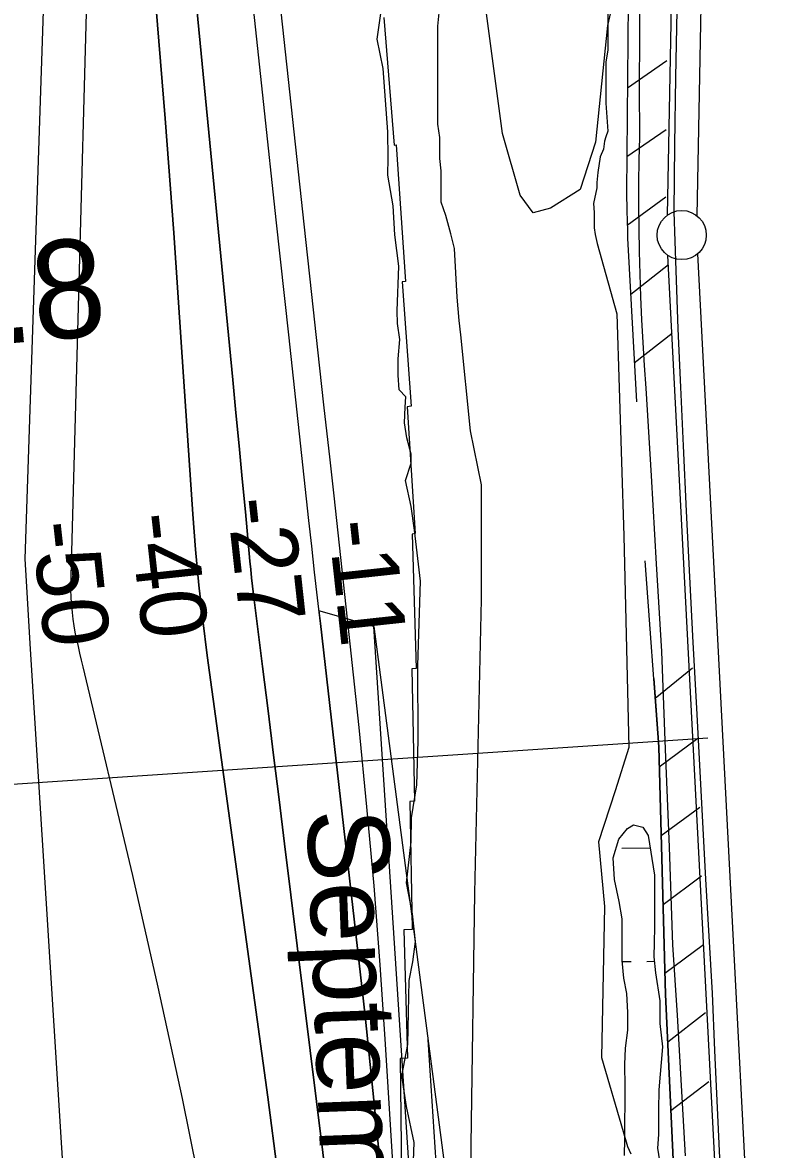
# Model space of a CAD drawing. Extents: x 3568792 to 3606828, y 529143 to 554785.
# Drawn here: x 3578425 to 3579198, y 535909 to 537056 of the extents above; entities that cross this region are included whole.
import ezdxf

# ---------------------------------------------------------------- set-up
doc = ezdxf.new("R2010")
doc.units = 0
for name, color, linetype in [('V-FLOD-BASE', 7, 'Continuous'), ('V-LEVE-TOET', 7, 'Continuous'), ('V-RIVR-EDGE', 7, 'Continuous'), ('V-RIVR-IDEN', 7, 'Continuous'), ('V-RIVR-RANG', 7, 'Continuous'), ('V-RRAP-FSHR', 7, 'Continuous'), ('V-RRAP-RVMT', 7, 'Continuous'), ('V-SITE-VEGE', 7, 'Continuous'), ('V-SURV-IDEN', 7, 'Continuous'), ('V-SURV-LINE', 7, 'Continuous'), ('V-TOPO-DPTH', 7, 'Continuous'), ('V-TOPO-MAJR', 7, 'Continuous'), ('V-TOPO-MINR', 7, 'Continuous'), ('V-WETL-SWMP', 7, 'Continuous')]:
    doc.layers.add(name, color=color, linetype=linetype)

msp = doc.modelspace()

# ---------------------------------------------------------------- linework, layer by layer
at = {"layer": 'V-FLOD-BASE'}
msp.add_lwpolyline([(3579092, 537136.5), (3579090.6, 537068.2), (3579089.3, 536999.9), (3579088.3, 536931.5), (3579087.4, 536863.2), (3579089.4, 536803.7), (3579091.7, 536744.2), (3579094.3, 536684.8), (3579097.1, 536625.3), (3579100.1, 536558.6), (3579103.3, 536491.8), (3579106.8, 536425.1), (3579110.4, 536358.4), (3579113.4, 536300.4), (3579116.5, 536242.4), (3579119.7, 536184.4), (3579123, 536126.5), (3579126.3, 536068.5), (3579128.8, 536010.2), (3579131.5, 535951.9), (3579134.4, 535893.6)], dxfattribs=at)
at = {"layer": 'V-LEVE-TOET'}
msp.add_lwpolyline([(3579052.7, 537091.9), (3579052.4, 537041), (3579052.3, 536990), (3579052.5, 536939.1), (3579052, 536915.9), (3579051.7, 536892.7), (3579051.7, 536869.4), (3579051.8, 536846.2), (3579052.2, 536823), (3579052.8, 536799.8), (3579053.6, 536776.6), (3579054.7, 536753.4), (3579055.9, 536730.2), (3579057.4, 536707), (3579059.1, 536683.9), (3579064.4, 536594.6), (3579069.6, 536505.3), (3579074.8, 536416.1), (3579078.8, 536316.6), (3579082.7, 536217.1), (3579086.2, 536117.7), (3579090.7, 536046.1), (3579095, 535974.6), (3579098.9, 535903)], dxfattribs=at)
at = {"layer": 'V-RIVR-EDGE'}
msp.add_lwpolyline([(3578821.6, 535860), (3578823.6, 535916.4), (3578815.7, 535953.2), (3578810.9, 535984.4), (3578817.1, 536016.3), (3578818.5, 536081.2), (3578822.2, 536100.2), (3578824.7, 536121.1), (3578821.7, 536149.2), (3578815.6, 536180.5), (3578820.6, 536222.2), (3578820.7, 536246.7), (3578826.3, 536280.4), (3578827.6, 536325.1), (3578827.2, 536401.7), (3578829.9, 536487.4), (3578823.9, 536539.5), (3578820.3, 536563.5), (3578814.8, 536589.8), (3578820.4, 536607.6), (3578820.4, 536616.8), (3578816.1, 536633.3), (3578813.7, 536648.6), (3578814.4, 536664.6), (3578815, 536675), (3578808.3, 536682.3), (3578807.1, 536697.1), (3578807.2, 536713.6), (3578809, 536733.2), (3578806.6, 536749.8), (3578806.1, 536762.6), (3578808, 536808), (3578803.8, 536839.8), (3578802, 536869.2), (3578796.6, 536900.5), (3578797.2, 536918.3), (3578796.7, 536944.6), (3578792, 537009), (3578785.9, 537039), (3578790.3, 537069.6)], dxfattribs=at)
at = {"layer": 'V-RIVR-RANG'}
msp.add_line((3579122.1, 536327.7), (3578124.3, 536261.4), dxfattribs=at)
at = {"layer": 'V-RRAP-FSHR'}
for p, q in [((3579040.2, 536989.4), (3579080.4, 537017.1)), ((3579039.6, 536919.4), (3579079.8, 536947.1)), ((3579040.1, 536849.5), (3579079.4, 536878.5)), ((3579043.6, 536779.5), (3579082, 536809.7)), ((3579047.3, 536709.6), (3579085.8, 536739.8)), ((3579068.5, 536368.5), (3579106.4, 536399.4)), ((3579072.7, 536298.7), (3579112, 536327.7)), ((3579074.6, 536228.7), (3579113.8, 536257.7)), ((3579076.5, 536158.7), (3579115.7, 536187.8)), ((3579078.3, 536088.7), (3579117.6, 536117.8)), ((3579081.2, 536018.8), (3579119.8, 536048.6)), ((3579084.4, 535948.9), (3579123.1, 535978.7))]:
    msp.add_line(p, q, dxfattribs=at)
for points in [[(3579046.3, 537362.9), (3579041.3, 537115.1), (3579039.2, 536882.9), (3579039.7, 536864.2), (3579040.3, 536844), (3579040.5, 536836.6), (3579049.5, 536670.1)], [(3579186.7, 534602.9), (3579174.2, 534707.2), (3579144.2, 534996.7), (3579130.5, 535127.8), (3579117, 535281.1), (3579108.5, 535490.5), (3579094.3, 535738.6), (3579078.9, 536066.9), (3579072.2, 536318.9), (3579058.2, 536508.1)], [(3579067.1, 536388.4), (3579072.2, 536318.9), (3579078.9, 536066.9), (3579094.3, 535738.6), (3579099, 535656.3)]]:
    msp.add_lwpolyline(points, dxfattribs=at)
at = {"layer": 'V-RRAP-RVMT'}
for p, q in [((3578792.8, 537060.9), (3578803.1, 536931.2)), ((3578803.1, 536931.2), (3578805.3, 536931.3)), ((3578805.3, 536931.3), (3578814.8, 536792.2)), ((3578814.8, 536792.2), (3578811.2, 536791.9)), ((3578811.2, 536791.9), (3578820.4, 536665.4)), ((3578820.4, 536665.4), (3578816.4, 536665)), ((3578816.4, 536665), (3578824.4, 536536)), ((3578824.4, 536536), (3578821.5, 536535.4)), ((3578821.5, 536535.4), (3578825.4, 536398.6)), ((3578825.4, 536398.6), (3578821.2, 536398.3)), ((3578821.2, 536398.3), (3578823.7, 536263.7)), ((3578823.7, 536263.7), (3578819, 536263.5)), ((3578819, 536263.5), (3578821.6, 536133.3)), ((3578821.6, 536133.3), (3578813, 536132.9)), ((3578813, 536132.9), (3578816.6, 536002.2)), ((3578816.6, 536002.2), (3578809.1, 536002.1)), ((3578809.1, 536002.1), (3578810.9, 535875))]:
    msp.add_line(p, q, dxfattribs=at)
at = {"layer": 'V-SITE-VEGE'}
for p, q in [((3578847.5, 537052.1), (3578849.7, 537072.5)), ((3579020.5, 537074.3), (3579020.5, 537027.9)), ((3578847.5, 536952.5), (3578847.5, 537052.1)), ((3579020.5, 537027.9), (3579018.3, 537015.4)), ((3579018.3, 537015.4), (3579018.3, 536973.6)), ((3579018.3, 536973.6), (3579020.5, 536945.2)), ((3578849.7, 536938.9), (3578847.5, 536952.5)), ((3579020.5, 536945.2), (3579018.3, 536939.6)), ((3578849.7, 536917.4), (3578849.7, 536938.9)), ((3579017.1, 536935.1), (3579016, 536927.1)), ((3579018.3, 536939.6), (3579017.1, 536935.1)), ((3579016, 536927.1), (3579012.6, 536919.2)), ((3578850.9, 536904.9), (3578849.7, 536917.4)), ((3579012.6, 536919.2), (3579010.3, 536903.4)), ((3578850.9, 536873.2), (3578850.9, 536904.9)), ((3579010.3, 536903.4), (3579009.2, 536893.2)), ((3579009.2, 536887.5), (3579005.8, 536871.7)), ((3579009.2, 536893.2), (3579009.2, 536887.5)), ((3578855.7, 536859.5), (3578850.9, 536873.2)), ((3579005.8, 536871.7), (3579006.6, 536862.6)), ((3578860.9, 536840.9), (3578855.7, 536859.5)), ((3579006.6, 536862.6), (3579006.6, 536847.1)), ((3579006.6, 536847.1), (3579007.6, 536840.3)), ((3578864.5, 536825.8), (3578860.9, 536840.9)), ((3579007.6, 536840.3), (3579009.4, 536831.1)), ((3579009.4, 536831.1), (3579029.4, 536759.3)), ((3578867.1, 536776.5), (3578864.5, 536825.8)), ((3578869.2, 536752.7), (3578867.1, 536776.5)), ((3578870.8, 536738.2), (3578869.2, 536752.7)), ((3579029.4, 536759.3), (3579036.6, 536533.8)), ((3578880.9, 536640.4), (3578870.8, 536738.2)), ((3578891.9, 536585.5), (3578880.9, 536640.4)), ((3578892, 536468.8), (3578891.9, 536585.5)), ((3579036.6, 536533.8), (3579041.8, 536318.2)), ((3578885.3, 536170.4), (3578892, 536468.8)), ((3579041.8, 536318.2), (3579027.9, 536274.3)), ((3579027.9, 536274.3), (3579010.9, 536222.4)), ((3579010.9, 536222.4), (3579017, 536156.6)), ((3578881.5, 535914), (3578885.3, 536170.4)), ((3579017, 536156.6), (3579014.1, 536002.9)), ((3579014.1, 536002.9), (3579036.1, 535927.7)), ((3579036.1, 535927.7), (3579040.4, 535912.6)), ((3578880.8, 535870), (3578881.5, 535914)), ((3579040.4, 535912.6), (3579043.6, 535905.1))]:
    msp.add_line(p, q, dxfattribs=at)
at = {"layer": 'V-SURV-LINE'}
for points in [[(3579080.9, 536859.9), (3579109.8, 538371.5)], [(3579139.8, 538370.9), (3579110.8, 536859.3)], [(3579167.9, 535153.4), (3579081.5, 536818.9)], [(3579111.5, 536820.4), (3579197.9, 535155)]]:
    msp.add_lwpolyline(points, dxfattribs=at)
msp.add_circle((3579095.5, 536839.6), 25, dxfattribs=at)
at = {"layer": 'V-TOPO-DPTH'}
for points in [[(3578568.1, 537426.5), (3578639.1, 536692.4), (3578642.3, 536658.8), (3578645.5, 536625.2), (3578648.7, 536591.6), (3578651.9, 536558), (3578656.5, 536507.8), (3578657.4, 536499.3), (3578658.2, 536490.8), (3578659.2, 536482.4), (3578660.2, 536473.9), (3578669.3, 536400.6), (3578674.9, 536355.6), (3578680.5, 536310.5), (3578686.1, 536265.4), (3578691.7, 536220.3), (3578776.4, 535537.7)], [(3578776.4, 535537.7), (3578691.7, 536220.3), (3578686.1, 536265.4), (3578680.5, 536310.5), (3578674.9, 536355.6), (3578669.3, 536400.6), (3578660.2, 536473.9), (3578659.2, 536482.4), (3578658.2, 536490.8), (3578657.4, 536499.3), (3578656.5, 536507.8), (3578651.9, 536558), (3578648.7, 536591.6), (3578645.5, 536625.2), (3578642.3, 536658.8), (3578639.1, 536692.4), (3578568.1, 537426.5)], [(3578791.6, 535866.8), (3578782.9, 535956.1), (3578773.5, 536045.4), (3578728.1, 536444.4), (3578725.1, 536470.6), (3578722.2, 536496.8), (3578719.3, 536523), (3578716.4, 536549.2), (3578695.9, 536738.1), (3578683.2, 536855.2), (3578670.6, 536972.4), (3578658.2, 537089.6)], [(3578560.7, 537074.2), (3578570.2, 536958.1), (3578579, 536841.8), (3578587.1, 536725.5), (3578598.5, 536555.6), (3578601.3, 536519.6), (3578604.6, 536483.6), (3578608.6, 536447.7), (3578613.1, 536411.9), (3578674.6, 535962.6), (3578684.5, 535886.5)], [(3578560.7, 537074.2), (3578570.2, 536958.1), (3578579, 536841.8), (3578587.1, 536725.5), (3578598.5, 536555.6), (3578601.3, 536519.6), (3578604.6, 536483.6), (3578608.6, 536447.7), (3578613.1, 536411.9), (3578674.6, 535962.6), (3578684.5, 535886.5)], [(3578774.2, 534596.2), (3578837.8, 535354.7), (3578839.7, 535380.4), (3578841.2, 535406.1), (3578842.2, 535431.8), (3578842.7, 535457.5), (3578842.9, 535470.1), (3578842.9, 535489.5), (3578842.6, 535508.9), (3578841.9, 535528.3), (3578840.8, 535547.7), (3578782.5, 536441.3), (3578726.6, 536457.5)], [(3578726.6, 536457.5), (3578728.1, 536444.4), (3578773.5, 536045.4), (3578782.9, 535956.1), (3578791.6, 535866.8), (3578798.9, 535777.3), (3578805.3, 535687.7), (3578816, 535520.7), (3578816.2, 535514.6), (3578816.1, 535508.5), (3578815.6, 535502.4), (3578814.8, 535496.3), (3578800.6, 535409.1), (3578793.1, 535359.3), (3578786.5, 535309.5), (3578781, 535259.5), (3578776.3, 535209.4), (3578726.7, 534595.8)], [(3578774.2, 534596.2), (3578837.8, 535354.7), (3578839.7, 535380.4), (3578841.2, 535406.1), (3578842.2, 535431.8), (3578842.7, 535457.5), (3578842.9, 535470.1), (3578842.9, 535489.5), (3578842.6, 535508.9), (3578841.9, 535528.3), (3578840.8, 535547.7), (3578782.5, 536441.3)], [(3578782.5, 536441.3), (3578892.7, 535600.9), (3578898.3, 535515), (3578898.4, 535512.5), (3578898.5, 535507.5), (3578898.5, 535502.6), (3578898.4, 535500.1), (3578898.1, 535495.1), (3578879.8, 535268.9), (3578877.3, 535154.1), (3578883.6, 535040.3), (3578896.8, 534964.6), (3578774.2, 534596.2)]]:
    msp.add_lwpolyline(points, dxfattribs=at)
at = {"layer": 'V-TOPO-MAJR'}
msp.add_lwpolyline([(3578610.9, 535847.1), (3578588.1, 535961.1), (3578563.3, 536074.6), (3578537.4, 536188), (3578487, 536400.3), (3578485.3, 536407.3), (3578483.7, 536414.3), (3578482.1, 536421.2), (3578480.4, 536428.2), (3578480.2, 536429), (3578478.9, 536435.6), (3578477.7, 536442.2), (3578476.8, 536448.9), (3578476.1, 536455.6), (3578475, 536467.6), (3578474.9, 536469.1), (3578474.7, 536473.9), (3578474.6, 536476), (3578474.5, 536480.2), (3578499.2, 537389.8)], dxfattribs=at)
at = {"layer": 'V-TOPO-MINR'}
for points in [[(3578776.4, 535537.7), (3578691.7, 536220.3), (3578686.1, 536265.4), (3578680.5, 536310.5), (3578674.9, 536355.6), (3578669.3, 536400.6), (3578660.2, 536473.9), (3578659.2, 536482.4), (3578658.2, 536490.8), (3578657.4, 536499.3), (3578656.5, 536507.8), (3578651.9, 536558), (3578648.7, 536591.6), (3578645.5, 536625.2), (3578642.3, 536658.8), (3578639.1, 536692.4), (3578568.1, 537426.5)], [(3578473.5, 535781.4), (3578433.5, 536418.4), (3578432.1, 536441.4), (3578430.7, 536464.4), (3578429.3, 536487.4), (3578428, 536510.4), (3578458.4, 537422.4)], [(3578824.4, 535529.8), (3578794.4, 536016.7), (3578788.9, 536097.3), (3578782.7, 536177.7), (3578775.4, 536258.1), (3578767.4, 536338.5), (3578758.4, 536423.8), (3578754.4, 536461.4), (3578750.3, 536499.1), (3578746.2, 536536.7), (3578742.1, 536574.3), (3578738, 536611.1), (3578731.8, 536667), (3578725.6, 536723), (3578719.5, 536779.1), (3578713.4, 536835.1), (3578654.3, 537380.1)], [(3578791.6, 535866.8), (3578782.9, 535956.1), (3578773.5, 536045.4), (3578728.1, 536444.4), (3578725.1, 536470.6), (3578722.2, 536496.8), (3578719.3, 536523), (3578716.4, 536549.2), (3578695.9, 536738.1), (3578683.2, 536855.2), (3578670.6, 536972.4), (3578658.2, 537089.6)], [(3578684.5, 535886.5), (3578674.6, 535962.6), (3578613.1, 536411.9), (3578608.6, 536447.7), (3578604.6, 536483.6), (3578601.3, 536519.6), (3578598.5, 536555.6), (3578587.1, 536725.5), (3578579, 536841.8), (3578570.2, 536958.1), (3578560.7, 537074.2)], [(3578774.2, 534596.2), (3578837.8, 535354.7), (3578839.7, 535380.4), (3578841.2, 535406.1), (3578842.2, 535431.8), (3578842.7, 535457.5), (3578842.9, 535470.1), (3578842.9, 535489.5), (3578842.6, 535508.9), (3578841.9, 535528.3), (3578840.8, 535547.7), (3578782.5, 536441.3)], [(3578797.4, 534596.4), (3578868.1, 535425.3), (3578869.1, 535439.3), (3578869.9, 535453.3), (3578870.4, 535467.3), (3578870.7, 535481.4), (3578870.7, 535495.4), (3578870.4, 535509.5), (3578869.9, 535523.5), (3578869.1, 535537.5), (3578837.6, 536021.1)]]:
    msp.add_lwpolyline(points, dxfattribs=at)
at = {"layer": 'V-WETL-SWMP'}
for p, q in [((3579034.5, 536216), (3579063.4, 536216.2)), ((3579035.1, 536100.5), (3579044.1, 536100.6)), ((3579060.1, 536100.7), (3579067.8, 536100.8))]:
    msp.add_line(p, q, dxfattribs=at)
msp.add_lwpolyline([(3578888.1, 537131.5), (3578900.6, 537253.2), (3578914.5, 537384.6), (3578918.6, 537533.9), (3578936.6, 537709.6), (3578939.4, 537894.9), (3578961.6, 538161.9), (3578974.1, 538222.7), (3578983.8, 538242.1), (3579000.4, 538253.1), (3579017, 538240.7), (3579032.2, 538226.9), (3579041.8, 538195.1), (3579047.4, 538154.9), (3579047.3, 537760.8), (3579044.5, 537279.4), (3579043, 537152.4), (3579019.9, 537052.8), (3579008, 536934), (3578992.1, 536886.1), (3578962.2, 536867.1), (3578944.3, 536862.1), (3578931.3, 536880.1), (3578913.2, 536942.9)], close=True, dxfattribs=at)
msp.add_lwpolyline([(3579037.3, 535903.3), (3579037.7, 535920), (3579037.7, 535937.4), (3579038.1, 535955.7), (3579037.9, 535973.4), (3579037.8, 535995.9), (3579038.4, 536012.3), (3579040.8, 536030.8), (3579040.8, 536048.7), (3579039.6, 536068.1), (3579036.6, 536083.6), (3579035, 536101.8), (3579035, 536124.2), (3579035, 536143.9), (3579031.8, 536161.7), (3579027.3, 536184), (3579025.9, 536206), (3579031.4, 536225.2), (3579040.2, 536235.8), (3579046.5, 536239.6), (3579055.8, 536237.2), (3579061.5, 536228.7), (3579067.7, 536188.3), (3579067.7, 536170.2), (3579067.7, 536146.9), (3579067.7, 536135.5), (3579067.5, 536119.9), (3579067.3, 536105.5), (3579068.9, 536089.2), (3579073.1, 536060.6), (3579073.1, 536037.5), (3579075.9, 536013.7), (3579072.2, 535970.1), (3579072, 535949.8), (3579072, 535924.8), (3579070.8, 535910.8), (3579073, 535897.8)], dxfattribs=at)

# ---------------------------------------------------------------- texts
at = {"layer": 'V-RIVR-IDEN'}
msp.add_text('September', height=83, rotation=272.2026, dxfattribs=at).set_placement((3578714.3, 536254.5))
at = {"layer": 'V-RIVR-RANG'}
for s, p in [('-27', (3578632.9, 536570.5)), ('-50', (3578434.3, 536546.4)), ('-40', (3578534, 536554.9)), ('-11', (3578735.9, 536547.7))]:
    msp.add_text(s, height=67, rotation=276.2141, dxfattribs=at).set_placement(p)
at = {"layer": 'V-SURV-IDEN'}
msp.add_text('5433+48.8', height=100, rotation=5.1054, dxfattribs=at).set_placement((3577879.7, 536681.8))

doc.saveas('drawing.dxf')
